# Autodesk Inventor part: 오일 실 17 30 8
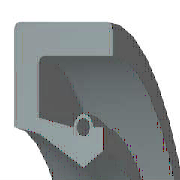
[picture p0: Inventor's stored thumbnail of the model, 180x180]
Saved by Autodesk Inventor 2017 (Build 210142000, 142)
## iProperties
IsCustomPart: 1
Created: 2012-02
Part Number: 오일 실 17 30 8
Material: 고무
Description: 오일-실
Document SubType Name: Modeling
Standard: KS B 2804
Designer: test
Standards Organization: KS
Language: ko-KR
Size Designation: S - 17 32 8
Categories: <MemberInstance><Categories><Category DisplayName="샤프트 부품" InternalName="7f7aeb1f-a693-4053-b835-cee3144e0d98" Mnemonic="SHFT"><Category DisplayName="실링" Intern
Density: 0.93 g/cm^3
Appearance: 고무 - 검은색 - 버전 1.1
Mass: 1.6913 g
Surface Area: 28.0102 cm^2
Volume: 1.81861 cm^3
Author: test
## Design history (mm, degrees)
revolve "본체" stored, may be unused: angle "d17" = 90 deg
revolve "스프링1" stored, may be unused: angle "d18" = 90 deg
body "Solid1"
sketch "스케치1"
  geometry: L1 (0, 15)-(8, 15); L2 (8, 15)-(8, 13.75); L3 (8, 13.75)-(1.75, 13.75); L4 (0, 15)-(0, 10.6); L5 (0, 10.6)-(1.75, 10.25); L6 (1.75, 10.25)-(4.9, 8.5); L7 (4.9, 8.5)-(0, 8.5); L8 (6.3, 9.375)-(6.3, 10.6); L9 (0, 0)-(9.586, 0) reference; L10 (4.9, 8.5)-(6.3, 9.375); L11 (0, 19.2)-(0, -3.2) reference; L12 (-1.917, 0)-(11.503, 0) reference; L13 (4.2, 10.6)-(1.75, 11.09); L14 (1.75, 11.09)-(1.75, 13.75); L15 (6.3, 10.6)-(5.6, 10.6); C1 r 0.455 at (4.9, 10.6); A1 r 0.7 centre (4.9, 10.6) between (5.6, 10.6) and (4.2, 10.6)
  constraints: 26 end point, 5 horizontal alignment, 4 perpendicular, 2 centre point, 2 collinear, 2 horizontal, 2 parallel, 2 point on circle, 2 point on line, 2 vertical alignment, 1 coincident
  dimensions: "d0" = 30 diameter of L1 L9 (= SD2); "d1" = 18.75 diameter of L8.start L9 (= ABDM); "d2" = 1.25 distance of L1.end L2.end (computed from SD); "d3" = 0.91 diameter of C1 (= SPDI); "d4" = 1.4 diameter of A1 (= SPDA); "d5" = 17 diameter of L6.end L9 (= NND); "d6" = 20.5 diameter of L5.end L9 (= TKDM); "d7" = 21.2 diameter of L4.end L9 (= HLDM); "d8" = 4.9 distance from line of C1.centre L4 (= SPDST); "d9" = 6.3 distance between parallel lines of L8 L4 (= SDI); "d10" = 8 distance between parallel lines of L2 L4 (= SWDT); "d12" = 1.75 distance between parallel lines of L14 L4 (= SD)
fillet "모깎기1" dims "d11" = 0.3 (= RR)
other parameters: "SD2" = 30 [user parameter; used in 1 equation term], "SWDT" = 8 [user parameter; used in 1 equation term], "RR" = 0.3 [user parameter; used in 1 equation term], "SD" = 1.75 [user parameter; used in 2 equation terms], "NND" = 17 [user parameter; used in 1 equation term], "SPDA" = 1.4 [user parameter; used in 1 equation term], "SPDI" = 0.91 [user parameter; used in 1 equation term], "TKDM" = 20.5 [user parameter; used in 1 equation term], "HLDM" = 21.2 [user parameter; used in 1 equation term], "ABDM" = 18.75 [user parameter; used in 1 equation term], "SDI" = 6.3 [user parameter; used in 1 equation term], "SPDST" = 4.9 [user parameter; used in 1 equation term], "d13" = 0, "d14" = 0, "d15" = 0, "LAB" = 0.35 [user parameter]
